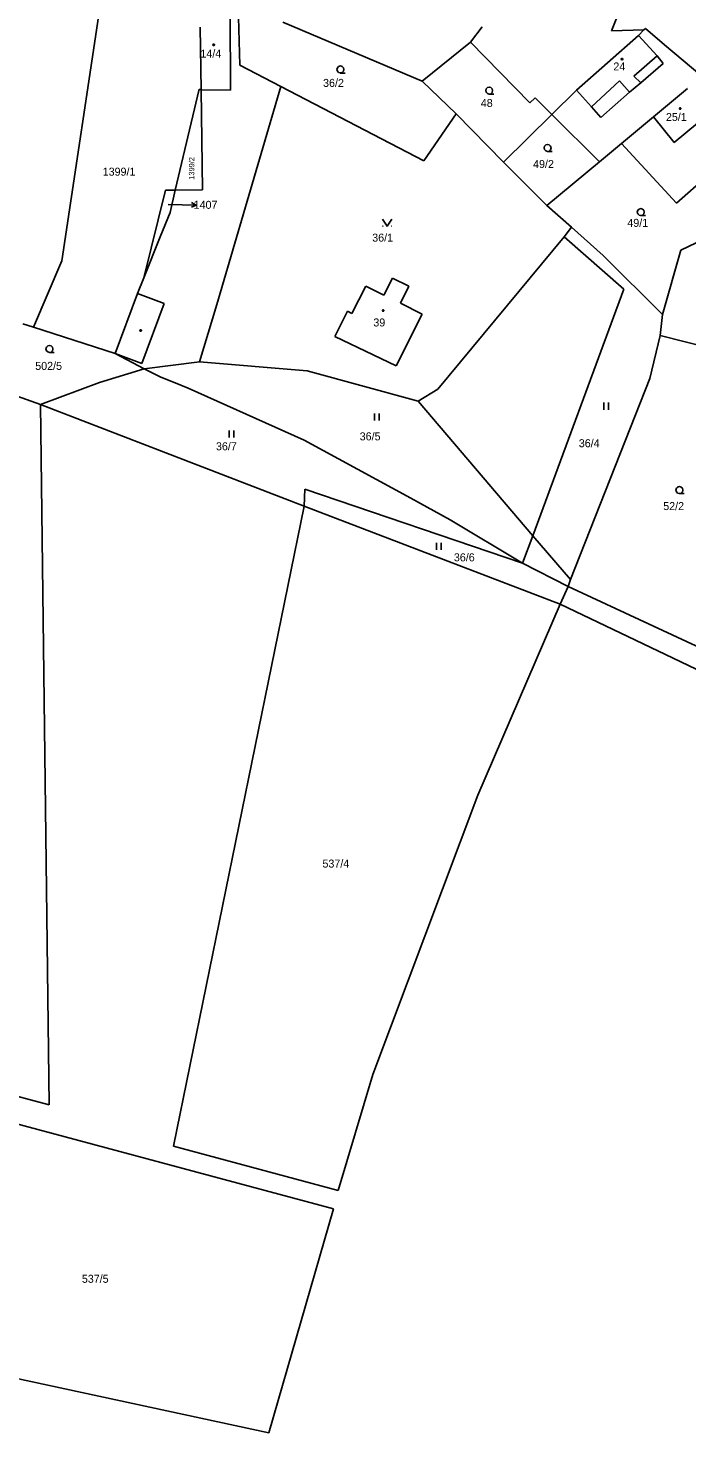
# Model space of a CAD drawing. Extents: x -852001 to -842497, y -1063614 to -1052182.
# Drawn here: x -844613.1 to -844473.2, y -1061824.6 to -1061526.1 of the extents above; entities that cross this region are included whole.
import ezdxf

# ---------------------------------------------------------------- set-up
doc = ezdxf.new("R2010")
doc.units = 0
for name, color, linetype in [('Default', 7, 'Continuous'), ('KN_HRANICE', 7, 'Continuous'), ('KN_KULTURY', 7, 'Continuous'), ('KN_PARCELY', 7, 'Continuous'), ('KN_SLUCKY', 7, 'Continuous')]:
    doc.layers.add(name, color=color, linetype=linetype)

# ---------------------------------------------------------------- blocks, each defined once
blk = doc.blocks.new('304')
at = {"layer": 'Default'}
blk.add_lwpolyline([(0, 0), (-0.38, 0.1), (-0.65, 0.37), (-0.75, 0.74), (-0.65, 1.11), (-0.38, 1.38), (-0.01, 1.48), (0.36, 1.38), (0.63, 1.11), (0.73, 0.73), (0.63, 0.35), (0.36, 0.08), (-0.02, -0.02), (0.98, -0.02)], dxfattribs=at)
blk = doc.blocks.new('306')
at = {"layer": 'Default'}
for p, q in [((-0.5, 1.5), (-0.5, 0)), ((0.5, 0), (0.5, 1.5))]:
    blk.add_line(p, q, dxfattribs=at)
blk = doc.blocks.new('314')
at = {"layer": 'Default'}
for p, q in [((-0.95, 0), (-0.85, 0)), ((0.85, 0), (0.95, 0))]:
    blk.add_line(p, q, dxfattribs=at)
blk.add_lwpolyline([(-1, 1.5), (0, 0), (1, 1.5)], dxfattribs=at)
blk = doc.blocks.new('10292')
at = {"layer": 'Default'}
blk.add_line((0, 3), (0, 0), dxfattribs=at)
blk.add_lwpolyline([(-0.5, 2), (0, 3), (0.5, 2)], dxfattribs=at)
blk = doc.blocks.new('402')
at = {"layer": 'Default'}
blk.add_lwpolyline([(0.09, 0.15), (0.18, 0), (0.09, -0.15), (-0.09, -0.15), (-0.18, 0), (-0.09, 0.15), (0.09, 0.15)], dxfattribs=at)

msp = doc.modelspace()

# ---------------------------------------------------------------- linework, layer by layer
at = {"layer": 'KN_HRANICE'}
for p, q in [((-844597.26, -1061517.65), (-844605.93, -1061575.54)), ((-844568.5, -1061521.23), (-844568.15, -1061533.97)), ((-844487.27, -1061521.98), (-844489.14, -1061526.71)), ((-844576.55, -1061525.94), (-844576.36, -1061539.23)), ((-844529.43, -1061537.42), (-844559.01, -1061524.82)), ((-844516.66, -1061525.83), (-844519.11, -1061529.08)), ((-844489.14, -1061526.71), (-844482.29, -1061526.47)), ((-844483.41, -1061527.66), (-844482.29, -1061526.47)), ((-844482.29, -1061526.47), (-844481.96, -1061526.18)), ((-844481.96, -1061526.18), (-844477.9, -1061529.66)), ((-844519.11, -1061529.08), (-844529.43, -1061537.42)), ((-844506.52, -1061542.01), (-844519.11, -1061529.08)), ((-844483.41, -1061527.66), (-844496.62, -1061539.27)), ((-844470, -1061536.35), (-844477.9, -1061529.66)), ((-844568.15, -1061533.97), (-844559.45, -1061538.5)), ((-844559.45, -1061538.5), (-844573, -1061584.86)), ((-844559.45, -1061538.5), (-844529.07, -1061554.3)), ((-844522.18, -1061544.31), (-844529.43, -1061537.42)), ((-844473.01, -1061538.94), (-844480.27, -1061544.97)), ((-844581.88, -1061560.53), (-844576.8, -1061539.11)), ((-844576.8, -1061539.11), (-844576.36, -1061539.23)), ((-844576.36, -1061539.23), (-844576.07, -1061560.49)), ((-844505.36, -1061540.96), (-844506.52, -1061542.01)), ((-844501.88, -1061544.47), (-844505.36, -1061540.96)), ((-844496.62, -1061539.27), (-844501.88, -1061544.47)), ((-844529.07, -1061554.3), (-844522.18, -1061544.31)), ((-844522.18, -1061544.31), (-844512.12, -1061554.6)), ((-844501.88, -1061544.47), (-844512.12, -1061554.6)), ((-844501.88, -1061544.47), (-844491.7, -1061554.5)), ((-844480.27, -1061544.97), (-844487.06, -1061550.63)), ((-844487.06, -1061550.63), (-844491.7, -1061554.5)), ((-844487.06, -1061550.63), (-844475.34, -1061563.31)), ((-844512.12, -1061554.6), (-844502.89, -1061563.82)), ((-844491.7, -1061554.5), (-844502.89, -1061563.82)), ((-844475.34, -1061563.31), (-844468.77, -1061557.5)), ((-844588.53, -1061579.17), (-844583.92, -1061560.55)), ((-844581.88, -1061560.53), (-844583.92, -1061560.55)), ((-844582.97, -1061565.26), (-844581.88, -1061560.53)), ((-844576.07, -1061560.49), (-844581.88, -1061560.53)), ((-844585.09, -1061570.48), (-844582.97, -1061565.26)), ((-844502.89, -1061563.82), (-844497.68, -1061568.39)), ((-844474.43, -1061573.26), (-844457.13, -1061564.94)), ((-844497.68, -1061568.39), (-844499.22, -1061570.46)), ((-844497.68, -1061568.39), (-844490.94, -1061574.45)), ((-844588.53, -1061579.17), (-844585.09, -1061570.48)), ((-844526.04, -1061602.85), (-844499.22, -1061570.46)), ((-844486.53, -1061581.59), (-844499.22, -1061570.46)), ((-844490.94, -1061574.45), (-844478.36, -1061586.95)), ((-844478.36, -1061586.95), (-844474.43, -1061573.26)), ((-844605.93, -1061575.54), (-844611.99, -1061589.68)), ((-844589.88, -1061582.52), (-844588.53, -1061579.17)), ((-844535.73, -1061579.25), (-844537.53, -1061582.84)), ((-844535.73, -1061579.25), (-844532.24, -1061580.97)), ((-844594.62, -1061595.27), (-844589.88, -1061582.52)), ((-844544.36, -1061586.72), (-844541.4, -1061580.94)), ((-844537.53, -1061582.84), (-844541.4, -1061580.94)), ((-844534.03, -1061584.57), (-844532.24, -1061580.97)), ((-844505.92, -1061633.98), (-844486.53, -1061581.59)), ((-844573, -1061584.86), (-844576.72, -1061597.05)), ((-844547.96, -1061591.63), (-844545.27, -1061586.24)), ((-844545.27, -1061586.24), (-844544.36, -1061586.72)), ((-844529.38, -1061586.87), (-844534.03, -1061584.57)), ((-844611.99, -1061589.68), (-844614.25, -1061588.91)), ((-844611.99, -1061589.68), (-844594.62, -1061595.27)), ((-844534.89, -1061597.88), (-844529.38, -1061586.87)), ((-844478.36, -1061586.95), (-844478.86, -1061591.44)), ((-844547.96, -1061591.63), (-844534.89, -1061597.88)), ((-844478.86, -1061591.44), (-844481.01, -1061600.53)), ((-844478.86, -1061591.44), (-844467.93, -1061594.19)), ((-844594.62, -1061595.27), (-844588.49, -1061598.47)), ((-844597.92, -1061601.39), (-844588.49, -1061598.47)), ((-844588.49, -1061598.47), (-844576.72, -1061597.05)), ((-844584.9, -1061600.24), (-844588.49, -1061598.47)), ((-844576.72, -1061597.05), (-844553.81, -1061598.96)), ((-844610.46, -1061606.05), (-844597.92, -1061601.39)), ((-844582.25, -1061601.32), (-844584.9, -1061600.24)), ((-844579.13, -1061602.62), (-844582.25, -1061601.32)), ((-844553.81, -1061598.96), (-844530.28, -1061605.39)), ((-844481.01, -1061600.53), (-844497.85, -1061643.25)), ((-844610.46, -1061606.05), (-844619.71, -1061602.81)), ((-844554.45, -1061613.63), (-844579.13, -1061602.62)), ((-844530.28, -1061605.39), (-844526.04, -1061602.85)), ((-844610.46, -1061606.05), (-844608.61, -1061754.86)), ((-844554.48, -1061627.7), (-844610.46, -1061606.05)), ((-844531.84, -1061625.95), (-844554.45, -1061613.63)), ((-844554.48, -1061627.7), (-844554.35, -1061624.06)), ((-844554.35, -1061624.06), (-844508.06, -1061639.77)), ((-844582.22, -1061763.64), (-844554.48, -1061627.7)), ((-844500.09, -1061648.51), (-844554.48, -1061627.7)), ((-844523.47, -1061630.59), (-844531.84, -1061625.95)), ((-844508.06, -1061639.77), (-844523.47, -1061630.59)), ((-844508.06, -1061639.77), (-844505.92, -1061633.98)), ((-844508.06, -1061639.77), (-844498.37, -1061644.75)), ((-844497.85, -1061643.25), (-844498.37, -1061644.75)), ((-844498.37, -1061644.75), (-844500.09, -1061648.51)), ((-844498.37, -1061644.75), (-844468.22, -1061658.79)), ((-844517.56, -1061689.06), (-844500.09, -1061648.51)), ((-844447.63, -1061673.57), (-844500.09, -1061648.51)), ((-844539.86, -1061748.43), (-844517.56, -1061689.06)), ((-844608.61, -1061754.86), (-844644.38, -1061745.28)), ((-844547.26, -1061773.08), (-844539.86, -1061748.43)), ((-844643.35, -1061751.43), (-844548.2, -1061776.97)), ((-844582.22, -1061763.64), (-844547.26, -1061773.08)), ((-844548.2, -1061776.97), (-844561.98, -1061824.56)), ((-844561.98, -1061824.56), (-844638.27, -1061808.11))]:
    msp.add_line(p, q, dxfattribs=at)
at = {"layer": 'KN_PARCELY'}
msp.add_line((-844583.39, -1061563.6), (-844580.38, -1061563.65), dxfattribs=at)
at = {"layer": 'KN_SLUCKY'}
for p, q in [((-844570.1, -1061539.27), (-844570.17, -1061523.06)), ((-844483.41, -1061527.66), (-844479.49, -1061532)), ((-844484.42, -1061536.3), (-844479.49, -1061532)), ((-844479.49, -1061532), (-844478.16, -1061533.64)), ((-844478.16, -1061533.64), (-844482.92, -1061537.75)), ((-844493.43, -1061542.82), (-844487.47, -1061537.35)), ((-844487.47, -1061537.35), (-844485.35, -1061539.76)), ((-844482.92, -1061537.75), (-844485.35, -1061539.76)), ((-844482.92, -1061537.75), (-844484.42, -1061536.3)), ((-844576.36, -1061539.23), (-844570.1, -1061539.27)), ((-844493.43, -1061542.82), (-844496.62, -1061539.27)), ((-844485.35, -1061539.76), (-844491.43, -1061545.1)), ((-844491.43, -1061545.1), (-844493.43, -1061542.82)), ((-844475.84, -1061550.39), (-844480.27, -1061544.97)), ((-844468.42, -1061544.28), (-844475.84, -1061550.39)), ((-844589.88, -1061582.52), (-844584.19, -1061584.62)), ((-844584.19, -1061584.62), (-844588.96, -1061597.37)), ((-844588.96, -1061597.37), (-844594.62, -1061595.27)), ((-844530.28, -1061605.39), (-844505.92, -1061633.98)), ((-844505.92, -1061633.98), (-844497.85, -1061643.25))]:
    msp.add_line(p, q, dxfattribs=at)

# ---------------------------------------------------------------- block references
at = {"layer": 'KN_KULTURY'}
for name, p in [('402', (-844573.68, -1061529.66)), ('402', (-844486.93, -1061532.7)), ('304', (-844546.77, -1061535.64)), ('304', (-844515.15, -1061540.13)), ('402', (-844474.57, -1061543.22)), ('304', (-844502.75, -1061552.31)), ('304', (-844482.94, -1061565.93)), ('314', (-844536.84, -1061568.2)), ('402', (-844537.67, -1061586.12)), ('402', (-844589.19, -1061590.38)), ('304', (-844608.58, -1061595.02)), ('306', (-844490.28, -1061607.18)), ('306', (-844539, -1061609.51)), ('306', (-844569.89, -1061613.07)), ('304', (-844474.74, -1061625)), ('306', (-844525.86, -1061636.94))]:
    msp.add_blockref(name, p, dxfattribs=at)
at = {"layer": 'KN_PARCELY', "rotation": -90.99631500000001}
msp.add_blockref('10292', (-844580.38, -1061563.65), dxfattribs=at)

# ---------------------------------------------------------------- texts
at = {"layer": 'KN_PARCELY'}
for s, height, p in [('14/4', 1.7, (-844576.51, -1061532.38)), ('24', 1.7, (-844488.78, -1061535.12)), ('36/2', 1.7, (-844550.45, -1061538.61)), ('48', 1.7, (-844516.94, -1061542.88)), ('25/1', 1.7, (-844477.61, -1061545.85)), ('1399/1', 1.7, (-844597.27, -1061557.47)), ('49/2', 1.7, (-844505.83, -1061555.84)), ('1407', 1.7, (-844577.95, -1061564.51)), ('1407', 0.1, (-844583.59, -1061563.65)), ('49/1', 1.7, (-844485.81, -1061568.34)), ('36/1', 1.7, (-844540.01, -1061571.48)), ('39', 1.7, (-844539.77, -1061589.5)), ('502/5', 1.7, (-844611.6, -1061598.73)), ('36/5', 1.7, (-844542.67, -1061613.7)), ('36/4', 1.7, (-844496.12, -1061615.16)), ('36/7', 1.7, (-844573.21, -1061615.81)), ('52/2', 1.7, (-844478.18, -1061628.51)), ('36/6', 1.7, (-844522.66, -1061639.4)), ('537/4', 1.7, (-844550.58, -1061704.46)), ('537/5', 1.7, (-844601.7, -1061792.67))]:
    msp.add_text(s, height=height, dxfattribs=at).set_placement(p)
msp.add_text('1399/2', height=1.14, rotation=89.496, dxfattribs=at).set_placement((-844577.83, -1061558.34))

doc.saveas('drawing.dxf')
